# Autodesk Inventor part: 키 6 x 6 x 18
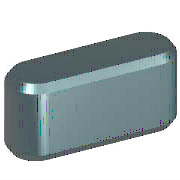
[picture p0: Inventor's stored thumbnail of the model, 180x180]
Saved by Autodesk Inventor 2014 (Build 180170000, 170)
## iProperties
IsCustomPart: 1
Created: 2012-02
Part Number: 키 6 x 6 x 18
Material: 강철, 연강
Description: 키 및 해당 키홈
Document SubType Name: Modeling
Standard: KS B 1311
Designer: mduedu
Standards Organization: KS
Language: ko-KR
Size Designation: 6 x 6 x 18
Categories: <MemberInstance><Categories><Category DisplayName="샤프트 부품" InternalName="7f7aeb1f-a693-4053-b835-cee3144e0d98" Mnemonic="SHFT"><Category DisplayName="키" Interna
Density: 1 g/cm^3
Appearance: 노란색
Author: mduedu
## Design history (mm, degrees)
workplane "Work Plane1"
workplane "Work Plane2"
sketch "스케치1"
  geometry: L1 (3, 3)-(15, 3); L2 (15, -3)-(3, -3); L3 (0, 9.4)-(0, -7.4) reference; L4 (-5, 0)-(30, 0) reference; L5 (18, 0)-(18, 7); A1 r 3 centre (3, 0) between (3, 3) and (3, -3); A2 r 3 centre (15, 0) between (15, -3) and (15, 3)
  constraints: 6 end point, 5 point on circle, 4 tangent, 3 point on line, 2 centre point, 1 horizontal, 1 parallel, 1 perpendicular
  dimensions: "d0" = 3 radius of A1 (= 0.5 x PB); "d13" = 3 radius of A2 (= 0.5 x PB); "d14" = 18 distance between parallel lines of L5 L3 (= NLG)
extrude "본체1" new body sketch "스케치1" taper "d3" = 0 deg; stored distance "d4" = 10
workplane "Work Plane3"
body "Solid1"
chamfer "모따기1" distance "d8" = 0.4 (= PHH); stored, may be unused: second distance "d9" = 0.4 (= PHH), angle "d15" = 45 deg
other parameters: "d1" = -3.5 (= -PNT), "d2" = 2.5 (= PH - PNT), "NLG" = 18 [user parameter; used in 3 equation terms], "PB" = 6 [user parameter; used in 2 equation terms], "PNT" = 3.5 [user parameter; used in 2 equation terms], "PH" = 6 [user parameter; used in 1 equation term], "PHH" = 0.4 [user parameter; used in 2 equation terms], "d10" = 0, "d16" = 0, "d17" = 0, "d18" = 0, "WDMIN" = 17 [user parameter], "PLB2" = 18 (= NLG) [user parameter], "WDMAX" = 22 [user parameter], "PLB1" = 18 (= NLG) [user parameter], "RR" = 0.16 [user parameter], "PUEB" = 2.8 [user parameter]
